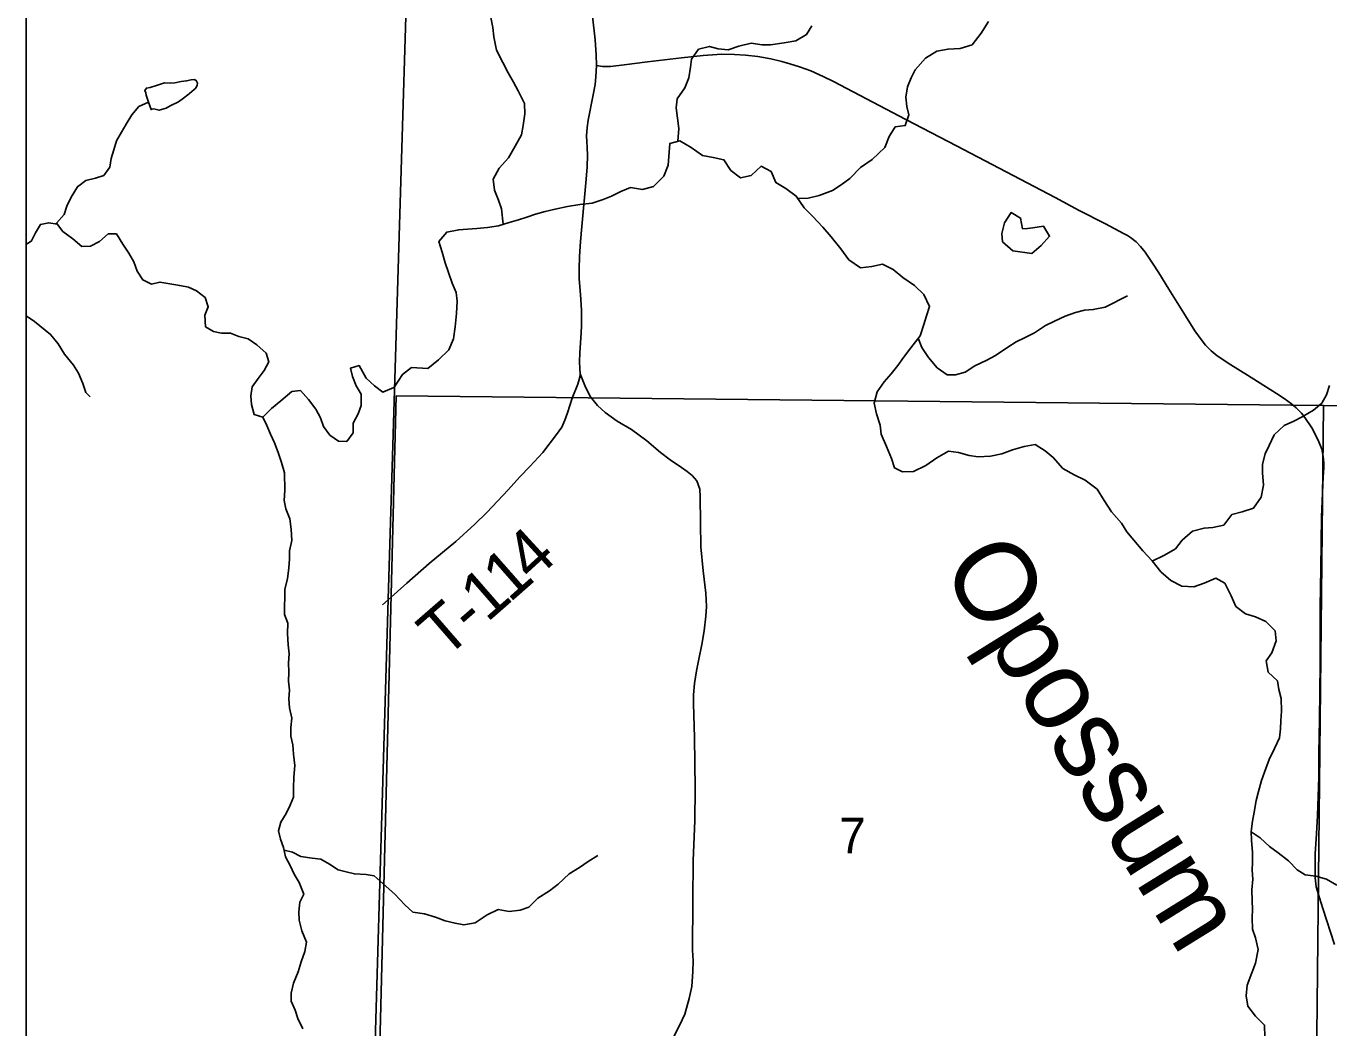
# Model space of a CAD drawing. Extents: x 0 to 191, y 0 to 55.
# Drawn here: x 143.275 to 144.045, y 22.997 to 23.589 of the extents above; entities that cross this region are included whole.
import ezdxf

# ---------------------------------------------------------------- set-up
doc = ezdxf.new("R2010")
doc.units = 0
for name, color, linetype in [('GM_X_Corporation', 7, 'Continuous'), ('GM_X_Minor_Lake', 7, 'Continuous'), ('GM_X_Minor_River', 7, 'Continuous'), ('GM_X_Minor_River_Text', 7, 'Continuous'), ('GM_X_Section_Text', 7, 'Continuous'), ('GM_X_State_Route', 7, 'Continuous'), ('GM_X_Township_Road', 7, 'Continuous'), ('GM_X_Township_Road_Text', 7, 'Continuous')]:
    doc.layers.add(name, color=color, linetype=linetype)

msp = doc.modelspace()

# ---------------------------------------------------------------- linework, layer by layer
at = {"layer": 'GM_X_Corporation'}
for points in [[(149.5758, 25.41761), (143.27549, 25.41761), (143.27549, 22.87347), (143.3138, 22.87294), (143.47809, 22.86847), (143.4892, 23.25041), (143.50802, 23.86711), (143.51777, 23.86795), (143.52133, 23.86809), (143.52783, 23.86865), (143.53573, 23.86991), (143.5371, 23.871), (144.17888, 23.85682), (144.27104, 23.85429), (144.35683, 23.85102), (144.94266, 23.83902)], [(145.79254, 25.41761), (143.27549, 25.41761), (143.27549, 22.87347), (143.3138, 22.87294), (143.47809, 22.86847), (143.4892, 23.25041), (143.50802, 23.86711), (143.51777, 23.86795), (143.52133, 23.86809), (143.52783, 23.86865), (143.53573, 23.86991), (143.5371, 23.871), (144.17888, 23.85682), (144.27104, 23.85429), (144.35683, 23.85102), (144.94266, 23.83902)], [(144.94266, 23.83902), (144.35683, 23.85102), (144.27104, 23.85429), (144.17888, 23.85682), (143.5371, 23.871), (143.53573, 23.86991), (143.52783, 23.86865), (143.52133, 23.86809), (143.51777, 23.86795), (143.50802, 23.86711), (143.4892, 23.25041), (143.47809, 22.86847), (143.3138, 22.87294), (143.27549, 22.87347), (143.27549, 18.61761)], [(144.77211, 22.85014), (144.13636, 22.86114), (144.1354, 22.86049), (144.13463, 22.85996), (144.13209, 22.85933), (144.12932, 22.85919), (144.12601, 22.85933), (144.11542, 22.85966), (144.09774, 22.86022), (144.07852, 22.8607), (144.05429, 22.8614), (144.03427, 22.86266), (144.0227, 22.86324), (143.96402, 22.86311), (143.61724, 22.8666), (143.61543, 22.86662), (143.47809, 22.86847), (143.4892, 23.25041), (143.50802, 23.86711)]]:
    msp.add_lwpolyline(points, dxfattribs=at)
for points in [[(144.04141, 23.36476), (144.03613, 22.86315), (143.48146, 22.86989), (143.49398, 23.37043)], [(144.54037, 23.35908), (144.5357, 22.85387), (144.03613, 22.86315), (144.04141, 23.36476)]]:
    msp.add_lwpolyline(points, close=True, dxfattribs=at)
at = {"layer": 'GM_X_Minor_Lake'}
for points in [[(143.37673, 23.55503), (143.37596, 23.55654), (143.37463, 23.55709), (143.37293, 23.55688), (143.37029, 23.55628), (143.36708, 23.55586), (143.3633, 23.55506), (143.36047, 23.55502), (143.35725, 23.55517), (143.35367, 23.55399), (143.34876, 23.55241), (143.3465, 23.55201), (143.34557, 23.55067), (143.34615, 23.54935), (143.34635, 23.54783), (143.34772, 23.54368)], [(143.34772, 23.54368), (143.34928, 23.53934), (143.34966, 23.53953), (143.35098, 23.53974), (143.35401, 23.53902), (143.35816, 23.54021), (143.36061, 23.54156), (143.3655, 23.5439), (143.36851, 23.54602), (143.37094, 23.54814), (143.37188, 23.54891), (143.37469, 23.55122), (143.37563, 23.55199), (143.37656, 23.55371), (143.37673, 23.55503)], [(143.86669, 23.46928), (143.86375, 23.46908), (143.86258, 23.47533), (143.85707, 23.47872), (143.85313, 23.47262), (143.85146, 23.46616), (143.85186, 23.46142), (143.85795, 23.45596), (143.86913, 23.45451)], [(143.86913, 23.45451), (143.87479, 23.4591), (143.87968, 23.46463), (143.87605, 23.47067), (143.86981, 23.4695), (143.86669, 23.46928)]]:
    msp.add_lwpolyline(points, dxfattribs=at)
at = {"layer": 'GM_X_Minor_River'}
for points in [[(143.55712, 23.47167), (143.55618, 23.4809), (143.55445, 23.48601), (143.55196, 23.49187), (143.55117, 23.49832), (143.55473, 23.50479), (143.56038, 23.51089), (143.56432, 23.51774), (143.56788, 23.5244), (143.56898, 23.52991), (143.56989, 23.53693), (143.56967, 23.543), (143.56603, 23.55038), (143.56316, 23.55548), (143.5601, 23.56115), (143.55685, 23.56721), (143.55322, 23.57439), (143.55166, 23.58235), (143.55106, 23.58785), (143.54989, 23.59372)], [(143.73122, 23.48682), (143.73717, 23.4871), (143.74378, 23.48866), (143.75153, 23.49155), (143.75663, 23.49499), (143.76172, 23.49863), (143.76812, 23.50511), (143.77491, 23.5099), (143.78245, 23.51696), (143.78506, 23.52343), (143.78863, 23.52914), (143.7945, 23.52993), (143.79655, 23.5362), (143.79538, 23.54113), (143.79478, 23.54663), (143.79589, 23.5527), (143.79794, 23.55803), (143.80038, 23.56278), (143.8064, 23.56965), (143.81319, 23.57386), (143.81981, 23.57504), (143.82701, 23.57546), (143.834, 23.57759), (143.83927, 23.58445), (143.84358, 23.59131)], [(143.66025, 23.52067), (143.66083, 23.52818), (143.66003, 23.53425), (143.65924, 23.5405), (143.65978, 23.54563), (143.66448, 23.55229), (143.66672, 23.55819), (143.66764, 23.56445), (143.66837, 23.5692), (143.6725, 23.5751), (143.67893, 23.57666), (143.68405, 23.57517), (143.68992, 23.57464), (143.69635, 23.57676), (143.70353, 23.57851), (143.70998, 23.5776), (143.7149, 23.57763), (143.72304, 23.57882), (143.72985, 23.58), (143.73626, 23.58364), (143.73926, 23.58878)], [(143.39625, 23.40742), (143.39095, 23.40736), (143.38621, 23.40844), (143.38145, 23.41122), (143.381, 23.41804), (143.38303, 23.42299), (143.38127, 23.42847), (143.37612, 23.43239), (143.37137, 23.4346), (143.36625, 23.43549), (143.35924, 23.43673), (143.3545, 23.43762), (143.3496, 23.43642), (143.34446, 23.43882), (143.34101, 23.44408), (143.33906, 23.44956), (143.33617, 23.45464), (143.33271, 23.4599), (143.32886, 23.46611), (143.32394, 23.46605), (143.31888, 23.46144), (143.31361, 23.45872), (143.30832, 23.45865), (143.30316, 23.46314), (143.29725, 23.46743), (143.29342, 23.47231), (143.2979, 23.47748), (143.29956, 23.48243), (143.30215, 23.48777), (143.30587, 23.49388), (143.31075, 23.49754), (143.31641, 23.49894), (143.32131, 23.50052), (143.32485, 23.5053), (143.32575, 23.51043), (143.32721, 23.51556), (143.32885, 23.52089), (143.33183, 23.52605), (143.33461, 23.53082), (143.33796, 23.53636), (143.34207, 23.54115), (143.34772, 23.54368), (143.34773, 23.54366)], [(143.49262, 23.3752), (143.49764, 23.38306), (143.50311, 23.38727), (143.51258, 23.38656), (143.51899, 23.39172), (143.52501, 23.39764), (143.52782, 23.4041), (143.52873, 23.41113), (143.52963, 23.4191), (143.52997, 23.42631), (143.52937, 23.43142), (143.52707, 23.43691), (143.52496, 23.44316), (143.52284, 23.44903), (143.5211, 23.45527), (143.51918, 23.46152), (143.52388, 23.46705), (143.53088, 23.46842), (143.53599, 23.46883), (143.54167, 23.46924), (143.54791, 23.46985), (143.55435, 23.47083), (143.56077, 23.47277), (143.56625, 23.47432), (143.57117, 23.47587), (143.57627, 23.4776), (143.58194, 23.47915), (143.58781, 23.48071), (143.59518, 23.48227), (143.60237, 23.48345), (143.60975, 23.48406), (143.61618, 23.48638), (143.62109, 23.4883), (143.62657, 23.49099), (143.63223, 23.49349), (143.63944, 23.4922), (143.64586, 23.49395), (143.65208, 23.50006), (143.65451, 23.50652), (143.65557, 23.51942), (143.66143, 23.52098), (143.66808, 23.51703), (143.67473, 23.51233), (143.68118, 23.51104), (143.68743, 23.50975), (143.69163, 23.50352), (143.69734, 23.49919), (143.70358, 23.50055), (143.70942, 23.5059), (143.71531, 23.5029), (143.71818, 23.49628), (143.72407, 23.4929), (143.73015, 23.48838), (143.73492, 23.48139), (143.73969, 23.47649), (143.74578, 23.47008), (143.75073, 23.46423), (143.75645, 23.45724), (143.76122, 23.45063), (143.76806, 23.44593), (143.77469, 23.44673), (143.78112, 23.4481), (143.78738, 23.4451), (143.79309, 23.44021), (143.79993, 23.4355), (143.80545, 23.43023), (143.8089, 23.42323), (143.80703, 23.41772), (143.80555, 23.41259), (143.80331, 23.40594), (143.79786, 23.39888), (143.79353, 23.39317), (143.79015, 23.38841), (143.7862, 23.38345), (143.78206, 23.37868), (143.77793, 23.37278), (143.77607, 23.36613), (143.77762, 23.35988), (143.77974, 23.35325), (143.78033, 23.34776), (143.7834, 23.34057), (143.78647, 23.33357), (143.78821, 23.32789), (143.79295, 23.32564), (143.79939, 23.32587), (143.80656, 23.32933), (143.81317, 23.33392), (143.81996, 23.33775), (143.82603, 23.33703), (143.83228, 23.33536), (143.83759, 23.33445), (143.84478, 23.33487), (143.85159, 23.33624), (143.85783, 23.33855), (143.86464, 23.34049), (143.87126, 23.34167), (143.87715, 23.3381), (143.8819, 23.33414), (143.88762, 23.32754), (143.89426, 23.32379), (143.90072, 23.32079)], [(143.29381, 23.47181), (143.28887, 23.47263), (143.28397, 23.47162), (143.28099, 23.46666), (143.27877, 23.46189), (143.27549, 23.45976)], [(143.80215, 23.40444), (143.80429, 23.39892), (143.8083, 23.39307), (143.81326, 23.38703), (143.81934, 23.38289), (143.82426, 23.38292), (143.82994, 23.38447), (143.8356, 23.38811), (143.84258, 23.39157), (143.84768, 23.39425), (143.85504, 23.39923), (143.85995, 23.40229), (143.86523, 23.40498), (143.87071, 23.40767), (143.87732, 23.41188), (143.8826, 23.41457), (143.88883, 23.41745), (143.89507, 23.41958), (143.90037, 23.42094), (143.90548, 23.42135), (143.91248, 23.42272), (143.92569, 23.42944)], [(143.27549, 23.41766), (143.2804, 23.41434), (143.28994, 23.40668), (143.29435, 23.40124), (143.2982, 23.39503), (143.30356, 23.38865), (143.30645, 23.38376), (143.30897, 23.37773), (143.31073, 23.37244), (143.3134, 23.36982)], [(143.43892, 22.99704), (143.43583, 23.00306), (143.43427, 23.00797), (143.43194, 23.01325), (143.43189, 23.01799), (143.43334, 23.02388), (143.43611, 23.03055), (143.43794, 23.03645), (143.44015, 23.04254), (143.44104, 23.04805), (143.43832, 23.05484), (143.43674, 23.06107), (143.4365, 23.066), (143.43701, 23.07169), (143.43942, 23.07646), (143.4367, 23.08325), (143.43381, 23.08814), (143.4313, 23.09341), (143.4286, 23.0985), (143.4274, 23.10398), (143.42565, 23.10889), (143.42446, 23.1138), (143.42592, 23.11894), (143.42909, 23.12409), (143.43131, 23.12886), (143.43334, 23.13362), (143.43328, 23.13912), (143.43359, 23.14556), (143.43409, 23.15239), (143.43345, 23.15902), (143.43301, 23.16451), (143.43183, 23.16961), (143.43177, 23.17473), (143.43247, 23.18023), (143.43109, 23.18628), (143.43065, 23.19177), (143.43098, 23.19671), (143.43035, 23.20201), (143.43068, 23.20751), (143.43043, 23.213), (143.43075, 23.21831), (143.43013, 23.22361), (143.42987, 23.23024), (143.43, 23.23631), (143.42805, 23.2414), (143.428, 23.24614), (143.42832, 23.25164), (143.42828, 23.25638), (143.42973, 23.26246), (143.4306, 23.26891), (143.43093, 23.27404), (143.43107, 23.27897), (143.43233, 23.28505), (143.43207, 23.29187), (143.43125, 23.29792), (143.42892, 23.30377), (143.42792, 23.30868), (143.42823, 23.31475), (143.42813, 23.32499), (143.42636, 23.33122), (143.42441, 23.33707), (143.42208, 23.34273), (143.41976, 23.34782), (143.41762, 23.35291), (143.4153, 23.35781), (143.41018, 23.35945), (143.4086, 23.36531), (143.40817, 23.37042), (143.40887, 23.37574), (143.4126, 23.38071), (143.41596, 23.38549), (143.41874, 23.39045), (143.41718, 23.39555), (143.41164, 23.4006), (143.40668, 23.40414), (143.401, 23.4054), (143.39625, 23.40742)], [(143.4153, 23.35781), (143.42035, 23.36299), (143.42598, 23.36761), (143.43236, 23.37299), (143.43746, 23.37363), (143.44224, 23.36838), (143.44646, 23.36255), (143.44935, 23.35747), (143.45111, 23.35238), (143.45476, 23.3473), (143.4599, 23.34376), (143.46482, 23.34345), (143.46855, 23.34861), (143.46868, 23.3543), (143.47146, 23.35983), (143.4733, 23.36478), (143.47323, 23.37141), (143.47035, 23.37631), (143.46821, 23.38197), (143.46702, 23.38688), (143.47211, 23.38827), (143.47635, 23.38093), (143.48113, 23.37644), (143.48608, 23.37271), (143.49262, 23.3753), (143.49262, 23.3752)], [(143.94035, 23.27282), (143.94754, 23.2765), (143.95396, 23.28015), (143.95791, 23.28529), (143.96413, 23.29064), (143.97093, 23.29239), (143.97604, 23.2928), (143.98248, 23.29417), (143.98736, 23.30045), (143.99342, 23.30201), (144.00003, 23.30413), (144.00454, 23.31061), (144.00602, 23.31783), (144.00541, 23.32503), (144.00538, 23.33015), (144.00705, 23.33623), (144.0093, 23.34118), (144.0123, 23.34745), (144.01814, 23.35299), (144.0238, 23.35549), (144.0289, 23.35799), (144.03551, 23.36201), (144.04041, 23.36621), (144.04322, 23.37097), (144.0449, 23.37648)], [(143.90072, 23.32079), (143.90775, 23.31533), (143.91196, 23.30872), (143.91616, 23.30211), (143.92225, 23.29532), (143.92531, 23.29021), (143.9295, 23.28531), (143.93484, 23.27908), (143.94017, 23.27305), (143.94532, 23.26663), (143.95122, 23.26154), (143.95786, 23.25817), (143.96487, 23.25783), (143.97092, 23.25996), (143.97791, 23.26284), (143.98323, 23.25984), (143.98687, 23.25247), (143.98974, 23.24622), (143.99544, 23.2419), (144.00132, 23.24004), (144.0074, 23.23723), (144.01292, 23.23176), (144.01352, 23.22589), (144.01091, 23.21885), (144.00752, 23.21409), (144.0087, 23.20746), (144.01422, 23.20237), (144.015, 23.19726), (144.01635, 23.19195), (144.01658, 23.18437), (144.01624, 23.17887), (144.01607, 23.17393), (144.01534, 23.16862), (144.01254, 23.16234), (144.00935, 23.15588), (144.0073, 23.15055), (144.00487, 23.14352), (144.00302, 23.13706), (144.00172, 23.13174), (144.00043, 23.12472), (143.99951, 23.11959), (143.99879, 23.11333), (143.99882, 23.10821), (143.99942, 23.101), (143.99945, 23.09531), (143.99929, 23.09057), (143.9997, 23.08526), (143.99916, 23.079), (143.99939, 23.07256), (143.99941, 23.06762), (143.99925, 23.0625), (143.99948, 23.05568), (144.00121, 23.05057), (144.00276, 23.04375), (144.00129, 23.03577), (143.99905, 23.03007), (143.99644, 23.02266), (143.99571, 23.01639), (143.99669, 23.01033), (144.00127, 23.00448), (144.0066, 22.9992), (144.00683, 22.992)], [(143.99879, 23.11314), (144.00411, 23.10957), (144.00944, 23.10448), (144.01457, 23.10091), (144.02066, 23.09601), (144.0258, 23.09073), (144.03055, 23.08792), (144.0368, 23.08701), (144.04325, 23.08534), (144.04933, 23.08177)], [(143.42777, 23.10231), (143.43273, 23.1012), (143.43767, 23.09861), (143.4443, 23.09774), (143.44942, 23.09705), (143.45456, 23.09408), (143.4597, 23.09073), (143.46444, 23.08965), (143.46937, 23.08839), (143.47618, 23.08809), (143.48092, 23.0872), (143.48458, 23.08415), (143.48458, 23.08406)], [(143.48458, 23.08415), (143.49323, 23.07636), (143.49913, 23.07014), (143.50389, 23.0658), (143.51071, 23.06489), (143.51716, 23.06285), (143.52285, 23.0606), (143.52873, 23.05931), (143.53385, 23.05839), (143.54066, 23.05957), (143.54764, 23.06416), (143.55425, 23.06743), (143.56069, 23.06614), (143.56712, 23.06693), (143.57223, 23.06867), (143.57769, 23.07401), (143.58448, 23.07841), (143.58958, 23.08224), (143.59617, 23.08834), (143.60221, 23.09217), (143.6073, 23.09562), (143.61296, 23.09925)]]:
    msp.add_lwpolyline(points, dxfattribs=at)
at = {"layer": 'GM_X_State_Route'}
for points in [[(143.61227, 23.56535), (143.61212, 23.57162), (143.61148, 23.5805), (143.60987, 23.59447), (143.60646, 23.62081), (143.60111, 23.6613), (143.59616, 23.70006), (143.59332, 23.72401), (143.59159, 23.73425), (143.58862, 23.74764), (143.58, 23.77739), (143.57491, 23.794), (143.5706, 23.8081), (143.56705, 23.81679), (143.56248, 23.82503), (143.55431, 23.83688), (143.54658, 23.8486), (143.54394, 23.85414), (143.54175, 23.8598), (143.53721, 23.87073)], [(144.04783, 23.04679), (144.04098, 23.06799), (144.03898, 23.07429), (144.03712, 23.08069), (144.03639, 23.086), (144.03656, 23.1002), (144.03726, 23.112), (144.03789, 23.1229), (144.03857, 23.1454), (144.03875, 23.15961), (144.03903, 23.17953), (144.03948, 23.21207), (144.03953, 23.23684), (144.03948, 23.24601), (144.03989, 23.26861), (144.0403, 23.29901), (144.0413, 23.32261), (144.04161, 23.32797), (144.04161, 23.33101), (144.0413, 23.33464), (144.04034, 23.33899), (144.03835, 23.3443), (144.03444, 23.35165), (144.03045, 23.35773), (144.02841, 23.36023), (144.02519, 23.36345), (144.02242, 23.36581), (144.0182, 23.3689), (144.01361, 23.37189), (143.99664, 23.38269), (143.9867, 23.38877), (143.97858, 23.39408), (143.97513, 23.39703), (143.97177, 23.40039), (143.96973, 23.40284), (143.96547, 23.40883), (143.95998, 23.41759), (143.95013, 23.43347), (143.94427, 23.44296), (143.94051, 23.44881), (143.93606, 23.45516), (143.93343, 23.45852), (143.9308, 23.46143), (143.92753, 23.46388), (143.92576, 23.46501), (143.9234, 23.46624), (143.91274, 23.47195), (143.89726, 23.4799), (143.88301, 23.48747), (143.84993, 23.50481), (143.8247, 23.51801), (143.79493, 23.53349), (143.7638, 23.54987), (143.75214, 23.55591), (143.74597, 23.55895), (143.7387, 23.56217), (143.73203, 23.56453), (143.72627, 23.56634), (143.72169, 23.56766), (143.7152, 23.56929), (143.70744, 23.57066), (143.70022, 23.57156), (143.69369, 23.57197), (143.6862, 23.57202), (143.67522, 23.57134), (143.66233, 23.56997), (143.64227, 23.56761), (143.62866, 23.5658), (143.62054, 23.56489), (143.61573, 23.56489), (143.61227, 23.56535)], [(143.65721, 22.99122), (143.66116, 22.99884), (143.66431, 23.00558), (143.66695, 23.01481), (143.66849, 23.02191), (143.66907, 23.03078), (143.66929, 23.03715), (143.669, 23.04345), (143.66915, 23.07261), (143.66937, 23.0962), (143.67032, 23.11964), (143.67054, 23.13869), (143.67003, 23.1688), (143.66951, 23.18865), (143.66959, 23.194), (143.67003, 23.20067), (143.67127, 23.20821), (143.67266, 23.2151), (143.6745, 23.22382), (143.67581, 23.23188), (143.67684, 23.24038), (143.67713, 23.24616), (143.67669, 23.254), (143.6753, 23.26719), (143.67391, 23.2814), (143.67354, 23.29554), (143.6734, 23.31093), (143.67325, 23.31539), (143.67142, 23.3203), (143.66864, 23.32338), (143.66585, 23.32587), (143.66248, 23.32822), (143.65567, 23.33276), (143.6501, 23.33708), (143.64197, 23.34382), (143.63296, 23.35063), (143.62439, 23.35561), (143.6208, 23.35803), (143.61728, 23.3606), (143.61274, 23.36477), (143.60871, 23.3699), (143.6057, 23.37561), (143.60259, 23.38339), (143.60233, 23.38638), (143.60212, 23.39078), (143.60233, 23.39591), (143.60314, 23.4077), (143.60343, 23.41181), (143.60337, 23.42102), (143.60272, 23.43035), (143.60208, 23.43956), (143.60202, 23.44542), (143.60227, 23.45263), (143.60285, 23.46152), (143.60356, 23.4704), (143.60614, 23.49822), (143.60672, 23.50562), (143.60691, 23.51257), (143.60678, 23.51708), (143.60646, 23.52049), (143.60639, 23.52397), (143.60672, 23.52873), (143.60723, 23.53305), (143.61032, 23.54805), (143.61142, 23.55417), (143.61193, 23.55867), (143.61227, 23.56535)]]:
    msp.add_lwpolyline(points, dxfattribs=at)
at = {"layer": 'GM_X_Township_Road'}
msp.add_line((143.48587, 23.24708), (143.48931, 23.25014), dxfattribs=at)
msp.add_lwpolyline([(143.48931, 23.25014), (143.50032, 23.25985), (143.51353, 23.27144), (143.52915, 23.28453), (143.54039, 23.29472), (143.54759, 23.30157), (143.56014, 23.31494), (143.56701, 23.32263), (143.57281, 23.32869), (143.5806, 23.33699), (143.58871, 23.34758), (143.59177, 23.35204), (143.59359, 23.35615), (143.59521, 23.36046), (143.59789, 23.36903), (143.60112, 23.37743), (143.60205, 23.38007), (143.60238, 23.38142), (143.60259, 23.38339)], dxfattribs=at)

# ---------------------------------------------------------------- texts
at = {"layer": 'GM_X_Minor_River_Text'}
msp.add_text('Opossum', height=0.047341, rotation=301.79448, dxfattribs=at).set_placement((143.81489, 23.26922))
at = {"layer": 'GM_X_Section_Text'}
msp.add_text('7', height=0.02093, rotation=0.00001, dxfattribs=at).set_placement((143.75553, 23.10055))
at = {"layer": 'GM_X_Township_Road_Text'}
for s, rotation, p in [('4', 42.46481, (143.57443, 23.2599)), ('1', 41.34761, (143.56085, 23.24794)), ('1', 41.08643, (143.54755, 23.23634)), ('T', 41.01175, (143.52268, 23.21471)), ('-', 41.03453, (143.53873, 23.22866))]:
    msp.add_text(s, height=0.02841, rotation=rotation, dxfattribs=at).set_placement(p)

doc.saveas('drawing.dxf')
